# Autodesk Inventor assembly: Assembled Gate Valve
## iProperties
Shininess: 64.0
Length Units: 11272
Angle Units: 11279
Time Units: 11290
Mass Units: 11286
Length Display Precision: 3
Angle Display Precision: 2
Compacted: True
Part Number: Assembled Gate Valve
Document SubType Name: Assembly
Created: 2003-10
Designer: jpittman
Manufacturer: Standard
Standards Organization: Custom
Density: 0.0
Volumn: 0.0
Area: 0.0
PropertySet Name: Model Information
Control State: 0
Master: False
Checked Out: False
Author: jpittman
